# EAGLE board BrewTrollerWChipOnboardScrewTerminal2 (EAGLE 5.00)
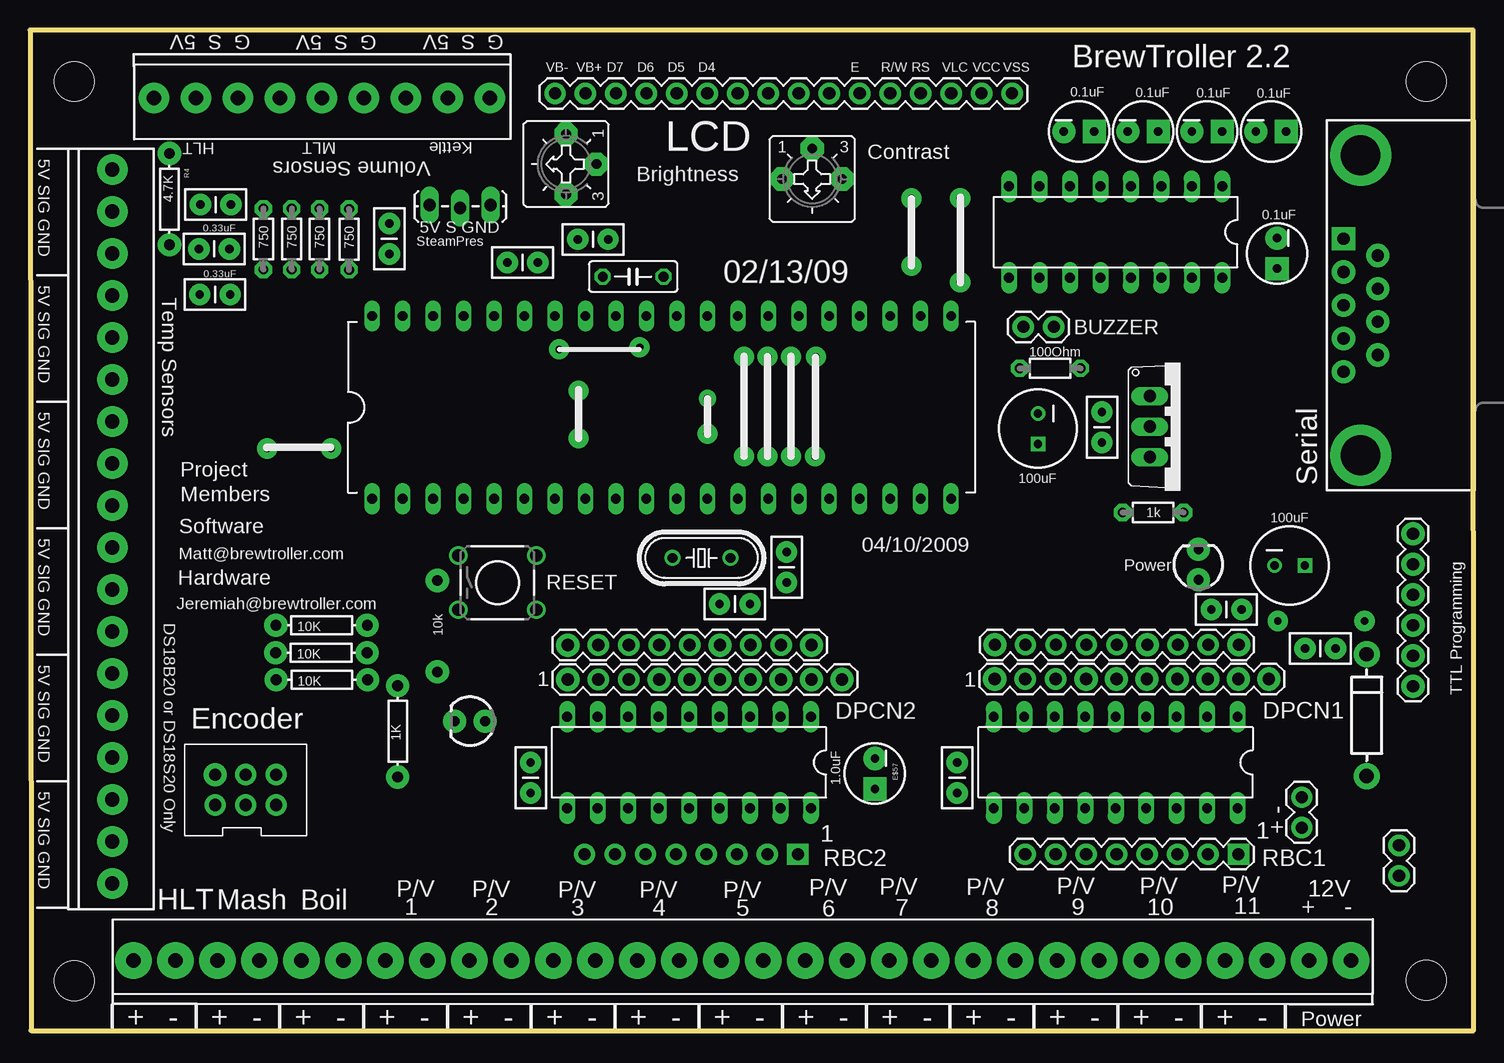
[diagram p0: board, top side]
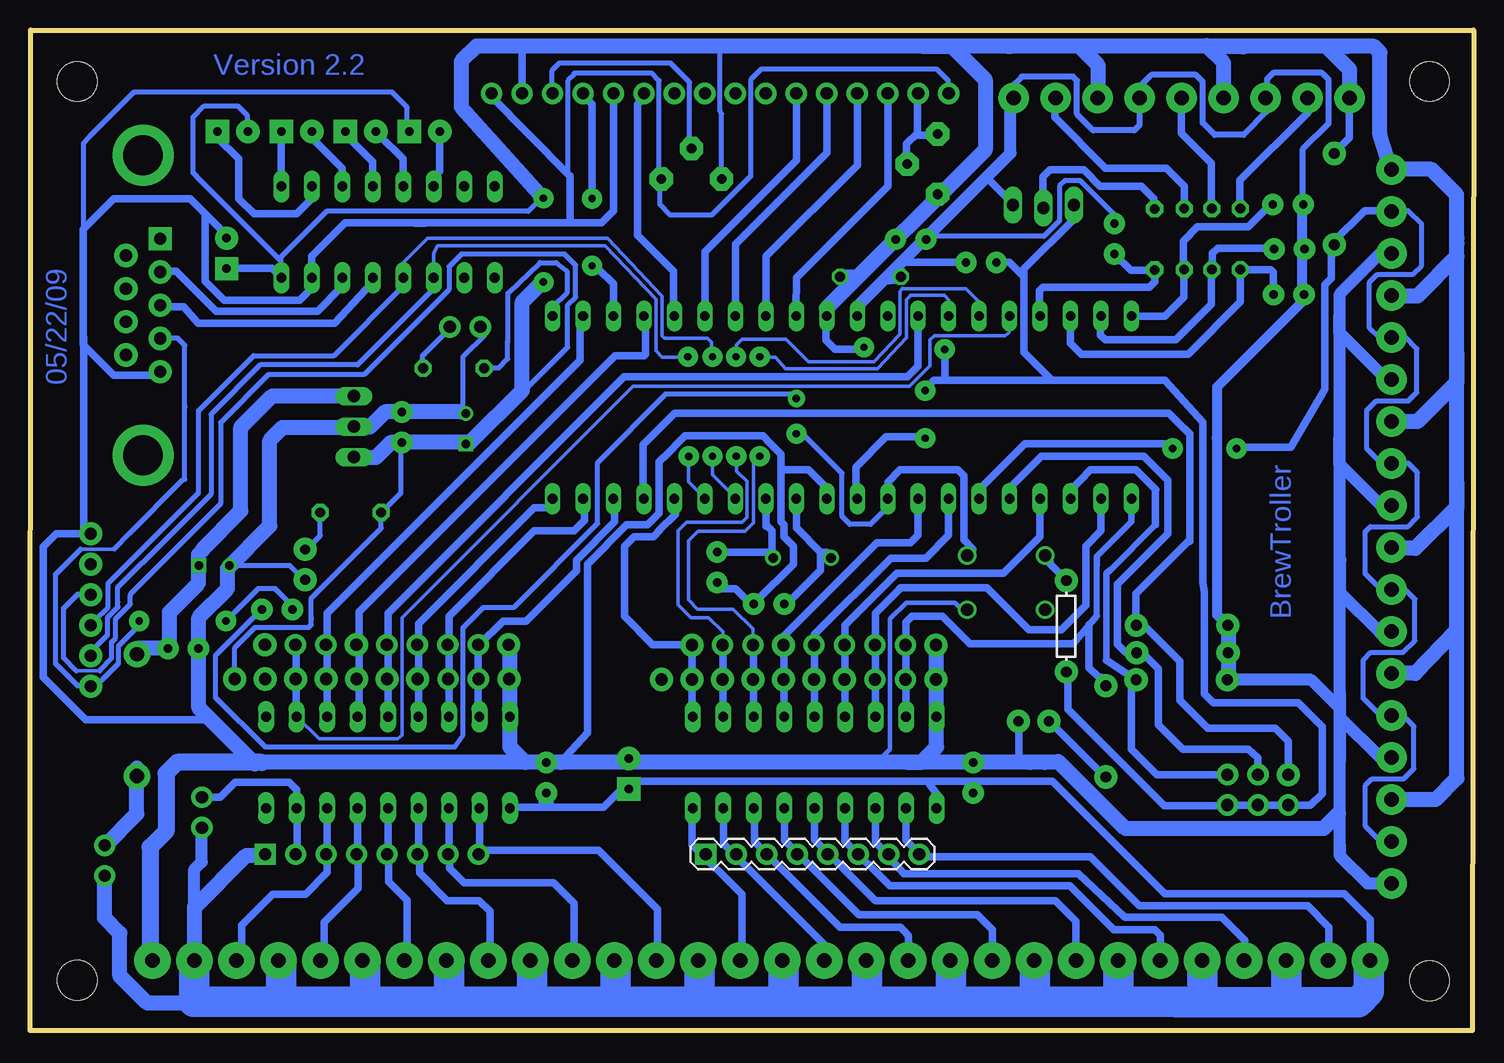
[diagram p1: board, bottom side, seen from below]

Size 120.35 x 83.39 mm. Coordinates in mm from the lower left corner, seen from the top.
Outline: 0.1,0 120.34,0 120.29,83.39 0,83.39 0.1,0
Copper layers (1*16): Top 0.035mm / dielectric 1.5mm / Bottom 0.035mm
Design rules "default *": minimum track width 10mil, minimum drill 24mil, track to track 8mil, track to pad 8mil, pad to pad 8mil, via to via 8mil, smd to smd 8mil, copper to edge 40mil, drill to drill 8mil, minimum pad ring 10mil, minimum via ring 8mil, stop-mask expansion 4mil, vias tented up to drill 0mil, thermal gap 10mil

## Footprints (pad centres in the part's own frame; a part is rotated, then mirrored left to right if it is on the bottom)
1X02 = drill 1.016 pad 1.778 round: 1 0,0; 2 2.54,0
LED3MM = drill 0.813 pad 1.93 round: A -1.27,0; K 1.27,0
HC49/S = drill 0.813 round: 1 -2.413,0; 2 2.413,0
DIL18 = drill 0.813 long: 1 -10.16,-3.81; 2 -7.62,-3.81; 3 -5.08,-3.81; 4 -2.54,-3.81; 5 0,-3.81; 6 2.54,-3.81; 7 5.08,-3.81; 8 7.62,-3.81; 9 10.16,-3.81; 10 10.16,3.81; 11 7.62,3.81; 12 5.08,3.81; 13 2.54,3.81; 14 0,3.81; 15 -2.54,3.81; 16 -5.08,3.81; 17 -7.62,3.81; 18 -10.16,3.81
DB9 = drill 1.016 pad 1.93 square: 1 -5.54,-1.42 | drill 1.016 pad 1.93 round: 2 -2.77,-1.42; 3 0,-1.42; 4 2.77,-1.42; 5 5.54,-1.42; 6 -4.15,1.42; 7 -1.38,1.42; 8 1.38,1.42; 9 4.15,1.42 | drill 3.302 pad 5.08 round: G1 -12.5,0; G2 12.5,0
SCREWTERMINAL3.5MM18P = drill 1.2 pad 2.54 round: 1 -31.496,0; 2 -27.996,0; 3 -24.496,0; 4 -20.996,0; 5 -17.496,0; 6 -13.996,0; 7 -10.496,0; 8 -6.996,0; 9 -3.496,0; 10 0.004,0; 11 3.504,0; 12 7.004,0; 13 10.504,0; 14 14.004,0; 15 17.504,0; 16 21.004,0; 17 24.504,0; 18 28.004,0
CAP-PTH-SMALL2 = drill 0.7 pad 1.778 round: 1 0,0; 2 2.54,0
2X3SHROUDEDHEADER = drill 1.02 pad 1.778 round: P$1 0,2.54; P$3 2.54,5.08; P$4 2.54,2.54; P$5 5.08,5.08; P$6 5.08,2.54 | drill 1.02 pad 1.93 round: P$2 0,5.08
C050-025X075 = drill 0.813 octagon: 1 -2.54,0; 2 2.54,0
DIL40 = drill 0.8 long: 1 -24.13,-7.62; 2 -21.59,-7.62; 3 -19.05,-7.62; 4 -16.51,-7.62; 5 -13.97,-7.62; 6 -11.43,-7.62; 7 -8.89,-7.62; 8 -6.35,-7.62; 9 -3.81,-7.62; 10 -1.27,-7.62; 11 1.27,-7.62; 12 3.81,-7.62; 13 6.35,-7.62; 14 8.89,-7.62; 15 11.43,-7.62; 16 13.97,-7.62; 17 16.51,-7.62; 18 19.05,-7.62; 19 21.59,-7.62; 20 24.13,-7.62; 21 24.13,7.62; 22 21.59,7.62; 23 19.05,7.62; 24 16.51,7.62; 25 13.97,7.62; 26 11.43,7.62; 27 8.89,7.62; 28 6.35,7.62; 29 3.81,7.62; 30 1.27,7.62; 31 -1.27,7.62; 32 -3.81,7.62; 33 -6.35,7.62; 34 -8.89,7.62; 35 -11.43,7.62; 36 -13.97,7.62; 37 -16.51,7.62; 38 -19.05,7.62; 39 -21.59,7.62; 40 -24.13,7.62
CPOL-RADIAL-100UF-25V = drill 0.7 square: 1 1.27,0 | drill 0.7 round: 2 -1.27,0
TO220V = drill 1.016 long: 1 -2.54,-2.54; 2 0,-2.54; 3 2.54,-2.54
0204/5 = drill 0.813 pad 1.422 octagon: 1 -2.54,0; 2 2.54,0
DIL16 = drill 0.813 long: 1 -8.89,-3.81; 2 -6.35,-3.81; 3 -3.81,-3.81; 4 -1.27,-3.81; 5 1.27,-3.81; 6 3.81,-3.81; 7 6.35,-3.81; 8 8.89,-3.81; 9 8.89,3.81; 10 6.35,3.81; 11 3.81,3.81; 12 1.27,3.81; 13 -1.27,3.81; 14 -3.81,3.81; 15 -6.35,3.81; 16 -8.89,3.81
CPOL-RADIAL-10UF-25V = drill 0.7 pad 1.93 square: 1 1.27,0 | drill 0.7 pad 1.93 round: 2 -1.27,0
SCREWTERMINAL3.5MM9P = drill 1.2 pad 2.54 round: 1 0.051,0.102; 2 3.551,0.102; 3 7.051,0.102; 4 10.551,0.102; 5 14.051,0.102; 6 17.551,0.102; 7 21.051,0.102; 8 24.551,0.102; 9 28.051,0.102
1X09 = drill 1.016 pad 1.93 round: 1 0,0; 6 12.7,0; 9 20.32,0 | drill 1.016 pad 1.778 round: 2 2.54,0; 3 5.08,0; 4 7.62,0; 5 10.16,0; 7 15.24,0; 8 17.78,0
1X08 = drill 1.016 pad 1.778 square: 1 0,0 | drill 1.016 pad 1.778 round: 2 2.54,0; 3 5.08,0; 4 7.62,0; 5 10.16,0; 6 12.7,0; 7 15.24,0; 8 17.78,0
1X16 = drill 1.016 pad 1.778 round: 1 0,0; 2 2.54,0; 3 5.08,0; 4 7.62,0; 5 10.16,0; 6 12.7,0; 7 15.24,0; 8 17.78,0; 9 20.32,0; 10 22.86,0; 11 25.4,0; 12 27.94,0; 13 30.48,0; 14 33.02,0; 15 35.56,0; 16 38.1,0
STAND-OFF = hole 3.302: 0,0
1X10 = drill 1.016 pad 1.93 round: 1 0,0; 4 7.62,0; 5 10.16,0; 6 12.7,0; 7 15.24,0; 8 17.78,0; 9 20.32,0; 10 22.86,0 | drill 1.016 pad 1.778 round: 2 2.54,0; 3 5.08,0
AXIAL-0.3 = drill 0.9 pad 1.93 round: P$1 -3.81,0; P$2 3.81,0
SCREWTERMINAL3.5MM30P = drill 1.2 pad 3.048 round: 1 0,0; 2 3.5,0; 3 7,0; 4 10.5,0; 5 14,0; 6 17.5,0; 7 21,0; 8 24.5,0; 9 28,0; 10 31.5,0; 11 35,0; 12 38.5,0; 13 42,0; 14 45.5,0; 15 49,0; 16 52.5,0; 17 56,0; 18 59.5,0; 19 63,0; 20 66.5,0; 21 66.5,0; 22 70,0; 23 73.5,0; 24 77,0; 25 80.5,0; 26 84,0; 27 87.5,0; 28 91,0; 29 94.5,0; 30 98,0; 31 101.5,0
CT6 = drill 0.813 pad 1.93 octagon: A 2.515,0; E -2.515,0; S 0,-2.54
1X03_LOCK_LONGPADS = drill 1.016 long: 1 0,0; 2 2.54,-0.254; 3 5.08,0
DIODE-1N4001 = drill 1.2 pad 2.184 round: A -5.08,0; C 5.08,0
TACTILE-PTH = drill 1.016 round: 1 -3.251,2.261; 2 3.251,2.261; 3 -3.251,-2.261; 4 3.251,-2.261
1X06 = drill 1.016 pad 1.93 round: 1 0,0; 2 2.54,0; 3 5.08,0; 4 7.62,0; 5 10.16,0; 6 12.7,0

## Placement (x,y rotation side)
BUZZER  [1X02]  82.8,58.65 0 top
E$1  Debug  [LED3MM]  36.68,25.78 180 top
E$2  16Mhz  [HC49/S]  55.98,39.4 180 top
E$3  ULN2803  [DIL18]  54.94,22.35 180 top
E$4  [DB9]  110.92,60.45 270 top
E$5  [SCREWTERMINAL3.5MM18P]  6.86,40.26 270 top
E$6  ULN2803  [DIL18]  90.5,22.35 180 top
E$7  0.33uF  [CAP-PTH-SMALL2]  16.69,61.34 180 top
E$8  [2X3SHROUDEDHEADER]  15.44,16.26 0 top
E$9  1uF  [C050-025X075]  50.28,62.83 180 top
E$10  ATMEGA644p  [DIL40]  52.65,51.94 0 top
E$11  100uF  [CPOL-RADIAL-100UF-25V]  105,38.76 0 top
E$12  100uF  [CPOL-RADIAL-100UF-25V]  84.02,50.16 270 top
E$13  0.1uF  [CAP-PTH-SMALL2]  108.84,31.85 180 top
E$14  0.1uF  [CAP-PTH-SMALL2]  89.36,49.02 90 top
E$15  22pF  [CAP-PTH-SMALL2]  63.07,37.34 90 top
E$16  22pF  [CAP-PTH-SMALL2]  57.48,35.56 0 top
E$17  7805  [TO220V]  95.88,50.34 270 top
E$18  [LED3MM]  97.41,38.84 90 top
E$19  1k  [0204/5]  93.62,43.18 0 top
E$20  MAX232  [DIL16]  90.5,66.55 180 top
E$21  0.1uF  [CPOL-RADIAL-10UF-25V]  98.12,74.93 0 top
E$22  0.1uF  [CPOL-RADIAL-10UF-25V]  92.79,74.93 0 top
E$23  0.1uF  [CPOL-RADIAL-10UF-25V]  103.45,74.93 0 top
E$24  [SCREWTERMINAL3.5MM9P]  38.38,77.83 180 top
E$25  750  [0204/5]  19.46,65.96 270 top
E$26  100nF  [CAP-PTH-SMALL2]  41.73,19.81 90 top
E$27  0.1uF  [CAP-PTH-SMALL2]  101.02,35.1 180 top
E$28  750  [0204/5]  21.82,65.96 270 top
E$29  750  [0204/5]  24.13,65.96 270 top
E$30  0.1uF  [CPOL-RADIAL-10UF-25V]  103.96,64.77 270 top
E$31  0.1uF  [CPOL-RADIAL-10UF-25V]  87.45,74.93 0 top
E$32  10k  [1X09]  44.83,32.13 0 top
E$33  750  [0204/5]  26.59,65.94 270 top
E$34  [1X08]  64.01,14.71 0 bottom
E$35  [1X08]  100.74,14.71 180 top
E$36  100Ohm  [0204/5]  85.04,55.19 180 top
E$37  10K  [1X09]  80.44,32.16 0 top
E$38  [1X16]  81.86,78.11 180 top
E$39  SteamHeat  [1X02]  106.02,16.92 90 top
E$40  [STAND-OFF]  3.68,4.17 0 top
E$41  [STAND-OFF]  3.68,79.1 0 top
E$42  [STAND-OFF]  116.41,79.1 0 top
E$43  [STAND-OFF]  116.41,4.19 0 top
E$44  [1X10]  44.83,29.26 0 top
E$45  [1X10]  80.42,29.31 0 top
E$46  0.33uF  [CAP-PTH-SMALL2]  29.95,67.26 270 top
E$47  100nF  [CAP-PTH-SMALL2]  77.29,19.81 90 top
E$48  0.33uF  [CAP-PTH-SMALL2]  16.64,65.15 180 top
E$49  0.33uF  [CAP-PTH-SMALL2]  16.74,68.83 180 top
E$50  10k  [AXIAL-0.3]  33.96,33.71 270 bottom
E$51  0.1uF  [CAP-PTH-SMALL2]  48.19,65.95 180 top
E$52  [SCREWTERMINAL3.5MM30P]  8.64,5.84 0 top
E$53  100Ohm  [CT6]  44.68,72.21 90 top
E$54  10K  [CT6]  65.2,70.97 180 top
E$55  1K  [AXIAL-0.3]  30.66,24.94 90 top
E$56  SteamPres  [1X03_LOCK_LONGPADS]  33.32,68.81 0 top
E$57  1.0uF  [CPOL-RADIAL-10UF-25V]  70.43,21.41 270 top
E$58  0.15uF  [CAP-PTH-SMALL2]  42.33,64.01 180 top
E$59  Switch  [1X02]  114.12,12.9 90 top
E$60  [DIODE-1N4001]  111.43,26.29 90 top
R1  10K  [AXIAL-0.3]  24.31,33.78 0 top
R2  10K  [AXIAL-0.3]  24.28,31.5 0 top
R3  10K  [AXIAL-0.3]  24.33,29.24 0 top
R4  4.7K  [AXIAL-0.3]  11.62,69.29 270 top
RESET  Reset  [TACTILE-PTH]  38.96,37.34 0 top
TTLPROG  DTR TX RX 5V N/C GND  [1X06]  115.29,28.7 90 top

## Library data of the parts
BUZZER E$1 E$3 E$4 E$6 E$7 E$10-E$18 E$20-E$23 E$26 E$27 E$30-E$32 E$34 E$35 E$37-E$51 E$55-E$60 R1-R4 RESET TTLPROG = SparkFun
E$2 = crystal
E$5 E$8 E$24 E$52 = Personal
E$9 = rcl
E$19 E$25 E$28 E$29 E$33 E$36 = rc-master
E$53 E$54 = pot

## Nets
S$22: E$3.5
S$65: E$10.13
S$105: E$6.11
S$255: E$3.9 E$6.9
S$257: E$39.1

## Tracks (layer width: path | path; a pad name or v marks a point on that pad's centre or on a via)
S$1
  Bottom 1.27: 93.29,52.91 100.15,52.91 102.77,50.29 102.77,43.31 105.94,40.13 105.94,40.06 106.3,39.7 106.3,37.29 108.71,34.87 108.71,32.16 108.74,31.88 111.23,31.88
S$2
  Bottom 0.61: 31.22,21.59 31.22,21.62 34.92,25.32
S$3
  Bottom 0.61: 67.82,41.73 68.38,41.17 70,41.17 70.79,40.39 70.79,36.02
S$4
  Bottom 0.61: 66.52,43.87 66.52,43.05 67.89,41.68
S$5
  Bottom 0.305: 63.55,56.29 63.55,57.38 63.86,57.68 67.44,57.68 67.64,57.91
S$6
  Bottom 0.61: 58.47,39.88 62.56,39.88
S$7
  Bottom 0.61: 62.81,36.83 61.54,36.83 60.53,35.81 59.77,35.81 56.72,38.86 56.72,40.39 57.48,41.15 57.48,42.16 57.73,42.42 57.73,46.48 57.48,46.74 55.45,46.74 53.92,45.21
S$8
  Bottom 0.381: 42.82,35.26 43.23,35.66 47.3,35.66 48.64,34.32 48.64,23.47 49.43,22.68 49.73,22.68
S$9  (via drill 0.6 pad 1.68)
  other vias: 63.45,47.88
S$10
  Bottom 0.61: 49.86,26.72 49.86,34.8 47.83,36.83
S$11
  Bottom 0.61: 52.4,33.02 52.4,33.78 48.08,38.1 39.19,38.1 36.14,41.15 36.14,44.04
S$12
  Bottom 0.61: 48.84,45.21 48.84,45.72 47.83,46.74 43,46.74 42.49,46.23 42.49,40.89 41.73,40.13
S$13
  Bottom 0.559: 31.42,34.57 33.38,32.26
  Bottom 0.61: 47.32,26.03 47.32,34.04 46.81,34.54 44.27,34.54 41.99,32.26 33.38,32.26
S$14
  Bottom 2.54: 27.64,2.41 106.71,2.41
S$15
  Bottom 0.61: 94.36,61.98 96.37,59.97 104.83,59.97 108.15,63.3 108.69,63.27
S$16
  Bottom 0.61: 33.6,45.01 31.95,46.74 28.14,46.74 26.49,45.08
S$17
  Bottom 0.61: 80.37,32.13 80.42,32.18
S$18
  Bottom 0.61: 52.4,26.47 52.4,32.89
S$19
  Bottom 0.61: 37.92,25.27 37.92,22.38 38,22.3
S$20
  Bottom 0.61: 38.81,45.08 36.02,47.88 27.51,47.88 25.48,45.85
S$21
  Bottom 0.61: 24.08,50.16 23.65,49.73 23.65,40.92 | 23.65,40.92 23.65,40.79 | 28.17,36.32 28.17,36.4 23.65,40.92
S$22
  Bottom 0.61: 43.76,43.69 43.76,41.27 45.67,39.37 48.59,39.37 54.94,33.02 E$3.5
S$23
  Bottom 0.61: 41.22,45.08 37.41,48.89 25.22,48.89
S$24
  Bottom 0.61: 99.44,62.79 100.18,63.53 103.66,63.53
S$25
  Bottom 0.61: 99.39,70.26 99.39,74.42
S$26
  Bottom 0.635: 80.4,18.61 72.53,18.61 70.37,20.76 45.54,20.76 44.78,19.75
S$27
  Bottom 2.54: 24.14,2.41 27.57,2.41
S$28
  Bottom 2.54: 29.6,3.24 29.6,5.84
S$29
  Bottom 2.54: 36.59,3.17 36.59,5.84
S$30
  Bottom 2.54: 43.57,3.11 43.57,5.84
S$31
  Bottom 2.54: 57.54,3.17 57.54,5.84
S$32
  Bottom 2.54: 64.53,2.79 64.53,5.84
S$33
  Bottom 2.54: 71.51,3.17 71.51,5.84
S$34
  Bottom 2.54: 78.5,3.11 78.5,5.84
S$35
  Bottom 2.54: 85.42,3.05 85.42,5.84
S$36
  Bottom 2.54: 92.41,3.17 92.41,5.84
S$37
  Bottom 2.54: 99.39,3.37 99.39,5.84
S$38  (via drill 0.6 pad 1.68)
  other vias: 25.1,48.51
S$39
  Bottom 2.54: 50.56,2.86 50.56,5.84
S$40
  Bottom 0.406: 107.44,45.95 107.44,52.04
S$41
  Bottom 0.61: 12.09,6.55 12.09,8.64 13.84,10.39 27.86,10.39 31.95,14.48 45.92,14.48 47.32,15.87 47.32,17.6 47.37,17.65
S$42
  Bottom 0.61: 19.07,6.53 19.07,7.52 21.01,9.45 29.08,9.45 32.97,13.06 47.47,13.06 49.86,15.72 49.86,17.6
S$43
  Bottom 0.61: 26.11,6.58 26.11,7.95 26.57,8.41 30,8.41 33.66,12.06 48.67,12.06 52.4,15.8 52.4,17.63 52.43,17.65
S$44
  Bottom 0.61: 54.97,17.7 54.89,17.63
S$45
  Bottom 0.61: 33.15,6.65 33.15,9.12 34.87,10.85 49.89,10.85 54.94,15.9 54.94,17.58 54.91,17.6
S$46
  Bottom 0.61: 40.13,6.58 40.13,8.41 41.38,9.65 51.23,9.65 57.43,15.85
S$47
  Bottom 0.61: 57.45,17.68 57.45,15.9
S$48
  Bottom 0.61: 82.91,17.58 82.88,17.6
S$49
  Bottom 0.61: 90.5,17.58 90.47,17.55
S$50
  Bottom 0.61: 88.9,5.87 88.9,10.87 90.45,12.42 90.45,15.14
S$51
  Bottom 0.61: 95.63,17.58 95.53,17.68
S$52
  Bottom 0.406: 81.84,78.05 81.89,78.1
S$53  (via drill 0.6 pad 1.68)
  other vias: 19.76,48.51
S$54
  Bottom 0.61: 46.3,43.56 46.3,41.27 46.94,40.64 49.73,40.64 57.48,32.89 57.48,25.91
S$55
  Bottom 0.61: 96.85,74.42 94.31,71.88 94.31,70.76
S$56
  Bottom 0.61: 93.8,74.42 91.77,72.39 91.77,70.79
S$57
  Bottom 0.61: 47.12,6.63 47.12,7.92 47.55,8.36 47.55,8.38 47.78,8.61 52.83,8.61 59.97,15.75 59.97,17.91
S$58
  Bottom 0.61: 56.46,44.2 56.46,41.91 54.43,39.88 | 54.43,39.88 53.92,39.88 | 54.43,39.88 54.43,38.35 56.97,35.81
S$59
  Bottom 0.61: 91.26,74.68 89.23,72.64 89.23,70.87
S$60
  Bottom 0.61: 86.69,71.12 86.18,71.63 86.18,74.68
S$61
  Bottom 0.61: 104.72,74.42 102.95,72.64 102.95,69.34 101.68,68.07 98.12,68.07 96.88,69.32 | 96.88,69.32 96.85,69.34 | 96.88,69.32 96.88,70.31
S$62
  Bottom 0.61: 92.3,61.77 94.94,58.95 106.32,58.95 107.52,60.32 108.84,60.32
S$63
  Bottom 1.016: 39.65,72.09 51.51,60.22 51.51,60.15 | 39.65,72.09 39.27,72.47 | 38.61,76.76 38.61,73.13 39.65,72.09
S$64
  Bottom 0.61: 69.24,44.83 69.24,48.82 66.6,51.46 25.43,51.46 23.67,49.71
S$65
  Bottom 0.61: 59,42.16 59,42.04 | 59,42.16 E$10.13 | 58.5,40 58.5,41.66 59,42.16
S$66
  Bottom 1.27: 92.79,47.75 91.52,47.75 90.25,49.02 83.64,49.02 79.32,53.34 79.32,60.71 77.65,62.38
S$67
  Bottom 0.813: 14.28,69.01 14.28,60.76 21.39,53.64 21.39,49.4 21.41,49.38
S$68
  Bottom 0.305: 64.06,44.37 65.43,45.75 65.43,47.88
S$69
  Bottom 0.61: 82.93,32.11 80.9,34.14 78.99,34.14 74.8,38.33 74.8,39.22 71.63,42.39 71.63,44.3
S$70
  Bottom 0.61: 74.12,43.56 74.12,42.54 75.01,41.66 78.31,41.66 85.42,34.54 85.42,26.03
S$71
  Bottom 0.61: 76.66,43.56 78.31,43.56 87.96,33.91 87.96,26.42
S$72
  Bottom 0.61: 53.9,44.4 53.9,45.14
S$73
  Bottom 0.61: 46.3,58.67 46.3,55.37 47.19,54.48 70.81,54.48 90.5,34.8 90.5,26.03
S$74
  Bottom 0.61: 69.04,58.8 69.04,56.39 69.16,56.26 71.58,56.26 92.91,34.92 92.91,26.54
S$75  (via drill 0.6 pad 1.68)
  other vias: 65.43,47.85
S$76
  Bottom 0.406: 76.73,60.32 75.59,61.47 75.59,63.3 76.48,64.01 77.83,64.01 80.49,61.47 80.49,57.4
S$77
  Bottom 0.61: 98.09,18.54 98.12,18.57 98.12,20.09 98.73,20.7 103.25,20.7 104.5,19.46 105.97,19.46
S$78  (via drill 0.6 pad 1.68)
  other vias: 63.45,56.16
S$79
  Bottom 1.016: 7.8,33.15 11.1,36.45 11.1,39.22
S$80
  Bottom 1.016: 7.75,43.79 11.2,47.24 11.2,49.33
S$81  (via drill 0.6 pad 1.68)
  other vias: 65.51,56.16
S$82
  Bottom 0.305: 61.49,44.37 63.45,46.33 63.45,47.96
S$83
  Bottom 0.61: 74.5,58.8 74.5,55.88 95.58,34.8 95.58,25.78
S$84
  Bottom 0.305: 65.79,56.13 67.64,56.13 68.17,56.64 68.17,60.96 72.41,65.4 86.36,65.4 86.69,64.77 86.69,63.5
S$85
  Bottom 0.305: 67.44,57.68 67.64,57.91 67.64,61.21 72.21,66.04 87.2,66.04 89.23,64.01 89.23,63.5
S$86
  Bottom 0.61: 50.95,56.77 53.24,56.77 53.98,57.53 53.98,59.54
S$87
  Bottom 0.406: 66.47,22.53 66.5,22.56
S$88  (via drill 0.6 pad 1.68)
  other vias: 73.48,63.75
S$89  (via drill 0.6 pad 1.68)
  Bottom 0.61: v73.48,69.34 73.48,77.19 73.81,77.52
S$90
  Bottom 0.61: 71.7,60.2 71.7,62.23 72.97,63.5
S$91
  Bottom 1.016: 7.34,54.33 11.2,58.19 11.2,59.51
S$92
  Bottom 0.61: 62.56,26.62 62.56,32.41
S$93
  Bottom 0.406: 4.72,42.75 5.46,42.01 8.61,42.01 9.04,41.58 9.04,38.07 7.8,36.83 5.77,36.83 4.9,35.97 4.9,32.51 5.89,31.52 8.56,31.52 9.22,30.86 9.22,27.69 7.8,26.26 5.89,26.26 4.98,25.35 4.98,21.84 5.84,20.98 8.48,20.98 9.02,20.45 9.02,17.02 7.77,15.77
S$94
  Bottom 0.61: 66.7,60.38 66.7,63.3 69.7,66.29 69.7,77.22 69.49,77.42
S$95
  Bottom 0.61: 96.85,63.5 96.85,64.52 94.06,67.31 72.72,67.31 71.7,68.33 71.7,77.47
S$96
  Bottom 0.61: 31.01,29.44 31.24,29.44 32.05,30.25 32.05,33.81
S$97
  Bottom 0.406: 5.44,68.3 4.34,67.21 4.34,63.75 5.08,63.02 8.03,63.02 8.69,62.36 8.69,58.55 7.92,57.78 5.66,57.78 4.72,56.85 4.72,53.19 5.44,52.48 8.13,52.48 8.89,51.71 8.89,48.49 7.7,47.29 5.46,47.29 4.7,46.53 4.7,42.8 4.72,42.77
S$98
  Bottom 0.61: 61.54,60.45 61.54,65.53 53.92,73.15 53.92,77.47
S$99
  Bottom 0.61: 58.98,59.94 59,64.52 51.38,72.14 51.38,77.47
S$100
  Bottom 1.27: 106.66,5.82 106.38,5.84
  Bottom 2.54: 106.66,2.44 106.66,5.82
S$101
  Bottom 0.61: 56.49,60.02 56.46,62.74 48.84,70.36 48.84,77.47
S$102  (via drill 0.6 pad 1.68)
  other vias: 77.55,62.38
S$103  (via drill 0.6 pad 1.68)
  other vias: 77.55,69.37
S$104
  Bottom 1.016: 7.72,64.82 11.15,61.39 11.15,28.04 | 11.15,15.44 11.15,14.55 8.84,12.24 6.86,12.24 | 11.15,15.44 11.15,28.04 | 7.8,22.78 11.15,26.14 11.15,28.04 | 11.15,15.44 11.15,14.6
S$105
  Bottom 0.61: E$6.11 82.88,15.06 82.91,15.04 72.95,15.04 68.25,10.34 68.22,10.34 68.02,10.13 68.02,5.84
S$106
  Bottom 0.61: 60.05,26.57 60.02,32.51
S$107
  Bottom 2.54: 24.79,2.39 9.63,2.39 8.74,3.28 8.74,5.79
S$108
  Bottom 2.54: 15.67,5.66 15.6,5.74
S$109
  Bottom 2.54: 17.42,2.36 16.64,2.36
S$110
  Bottom 0.406: 22.62,5.78 22.75,5.91
  Bottom 2.54: 22.62,3.87 22.62,5.78
S$111
  Bottom 2.54: 15.6,2.46 15.6,5.84
S$112
  Bottom 1.27: 34.54,22.35 36.98,22.35
S$113
  Bottom 0.61: 54.08,6.65 54.08,7.14 62.53,15.6 62.53,17.73
S$114
  Bottom 0.61: 61.01,6.58 61.01,11.35 65.15,15.49 65.15,17.65 65.1,17.7
S$115
  Bottom 0.61: 75.01,5.87 75.01,10.62 76.71,12.32 84.15,12.32 85.37,13.54 85.37,14.99 85.4,15.01
S$116
  Bottom 0.305: 61.42,47.88 61.44,47.85 61.44,46.63 60.58,45.77 60.58,42.77 60.98,42.37 65.61,42.37 66.32,41.66 66.32,35.51 65.23,34.42 63.78,34.42 62.59,33.22 62.59,32.03
S$117
  Bottom 1.27: 10.54,82.02 8.31,82.02 7.82,81.53 7.82,74.65 6.86,71.65
S$118
  Bottom 1.27: 6.25,29.77 4.85,29.77 1.42,33.38 1.42,36.17
S$119
  Bottom 0.61: 45.41,53.77 44.98,54.2 42.93,54.2 | 42.93,54.2 43.66,54.2 | 35.15,54.2 25.76,54.2 22.58,50.7 22.58,37.36 22.45,36.55 22.45,28.07 21.69,27.3 14.61,27.3 12.62,25.32 12.62,19.76 13.61,18.77 21.03,18.77 | 35.15,54.2 42.93,54.2 | 35.15,54.2 37.49,56.54 37.49,63.47 33.38,67.59 33.38,69.01
S$120
  Bottom 0.61: 7.34,68.33 9.09,68.33 11.86,65.56 11.86,62.71 12.42,62.15 12.42,53.47 15.24,48.62 19.48,48.62 19.63,48.46
S$121
  Bottom 0.61: 21.21,21.34 26.42,21.34 28.52,23.44 28.52,28.5 28.47,28.55
S$122
  Bottom 0.61: 18.01,21.95 18.01,22.76 18.8,23.44 24.26,23.44 26.29,25.48 26.29,30.15 27.58,31.45
S$123
  Bottom 0.61: 15.47,22.1 15.47,24.13 16.54,25.2 22.15,25.2 24.49,27.53 24.49,30.78 27.48,33.78
S$124
  Bottom 0.559: 30.33,38.38 30.61,38.1 30.61,30.86
  Bottom 0.61: 28.78,29.64 30.61,30.86
S$125
  Bottom 0.61: 25.48,45.8 25.48,41.43 29.69,37.21 29.69,32.21 29.03,31.55
S$126
  Bottom 0.61: 28.17,34.44 28.17,36.25
S$127
  Bottom 1.27: 20.4,33.78 20.4,29.21 20.45,29.16
S$128
  Bottom 1.27: 20.27,33.73 20.17,33.83
S$129  (via drill 0.6 pad 1.68)
  other vias: 45.72,53.34
S$130  (via drill 0.6 pad 1.68)
  other vias: 45.72,49.38
S$131
  Bottom 0.61: 51.51,44.65 51.51,46.94 48.97,49.48 46.23,49.48 46.1,49.35
S$132
  Bottom 0.61: 65.15,26.67 65.15,32
S$133
  Bottom 0.61: 16.71,68.86 16.92,68.86 18.8,66.98 23.01,66.98 24.21,65.79 24.21,63.5
S$134
  Bottom 1.27: 19.2,81.99 21.39,81.99
S$135
  Bottom 1.27: 53.98,60.17 40.72,73.41 40.72,79.25 43.51,82.04 46.05,82.04 | 77.52,69.32 84.4,76.96 84.4,80.77 83.13,82.04 46.05,82.04 | 38.96,82.04 46.05,82.04 | 38.96,82.04 38.43,82.04 | 9.73,82.04 38.96,82.04
S$136
  Bottom 1.27: 29.97,82.04 31.09,82.04
S$137
  Bottom 1.27: 1.4,65.61 1.42,69.67 3.53,71.78 6.91,71.78 6.93,71.75
S$138
  Bottom 0.61: 28.04,59.54 25.73,59.54 24.16,61.11 24.16,63.45 24.18,63.47
S$139
  Bottom 0.61: 93.04,17.65 92.99,17.7
S$140
  Bottom 0.61: 92.99,15.06 92.99,11.86 95.81,9.04 95.81,5.87 95.88,5.79
S$141
  Bottom 0.61: 81.99,5.84 81.99,9.93 82.91,10.85 85.57,10.85 87.88,13.16 87.88,15.09
S$142
  Bottom 0.61: 95.56,15.11 95.56,13.18 97.36,11.38 100.13,11.38 102.72,8.79 102.72,5.99 102.82,5.89
S$143
  Bottom 0.61: 85.4,15.06 85.4,18.54 85.47,18.62
S$144
  Bottom 0.61: 87.94,15.06 87.94,18.54
S$145
  Bottom 0.61: 90.5,15.11 90.5,18.49 90.58,18.57
S$146
  Bottom 0.61: 93.01,15.11 93.01,18.44 92.84,18.62 92.89,18.62
S$147
  Bottom 0.61: 95.58,15.01 95.58,18.54 95.56,18.57
S$148
  Bottom 1.016: 20.68,29.26 20.65,29.24 13.54,29.24 11.12,26.82 11.12,22.53
S$149
  Bottom 1.27: 6.17,40.16 6.15,40.18 4.85,40.18 1.4,43.64 1.4,45.59 | 5.99,61.21 4.7,61.21 1.4,64.52 | 6.07,50.75 4.7,50.75 1.4,54.05 1.4,56.44 | 1.4,64.52 1.4,66.04 | 1.4,56.44 1.4,64.52 | 1.4,45.59 1.4,56.44 | 1.4,45.59 1.4,21.03 3.17,19.25 6.96,19.25
S$150
  Bottom 1.27: 31.29,77.72 31.29,80.44 32.92,82.07
S$151
  Bottom 1.27: 20.83,77.7 20.83,80.64 22.28,82.09
S$152
  Bottom 0.61: 16.64,65.2 21.34,65.2 21.77,64.77 21.77,63.65 21.87,63.55
S$153
  Bottom 0.61: 16.69,61.39 16.69,63.2 16.89,63.4 19.25,63.4 19.33,63.47
S$154
  Bottom 0.813: 20.52,33.78 21.39,34.65 21.39,49.86
S$155
  Bottom 1.27: 10.34,77.72 10.34,80.09 12.27,82.02
S$156
  Bottom 0.61: 13.84,77.67 13.84,76.5 19.48,70.87 19.48,68.58
S$157
  Bottom 0.61: 96.88,61.87 97.87,60.88 104.16,60.88 105.74,62.46 105.74,68.07 | 109.55,54.86 109.8,54.61 113.36,54.61 115.9,57.15 115.9,66.8 113.36,69.34 107.01,69.34 105.74,68.07 | 105.74,68.07 103.96,66.29
S$158
  Bottom 0.61: 21.87,60.53 24.84,57.56 30.71,57.56 31.11,57.96 31.11,58.62
S$159
  Bottom 0.61: 19.48,60.68 23.77,56.39 32.72,56.39 33.63,57.3 33.63,58.78
S$160
  Bottom 0.61: 38.56,73.02 38.56,74.65
S$161
  Bottom 0.305: 38.76,59.31 38.76,58.17 39.09,57.91 44.96,57.91 45.31,57.56 45.31,55.42 47.04,53.7 70.08,53.7 89.33,34.42 89.33,24.64 89.69,24.31 96.24,24.31 98.15,26.21
S$162
  Bottom 0.61: 98.17,26.09 98.17,32.05 98.3,32.18 98.27,32.18 98.2,32.26
S$163
  Bottom 0.305: 47.6,61.85 47.83,61.57 47.83,58.01 49.99,55.73 55.45,55.73
S$164
  Bottom 0.305: 46.96,61.24 47.3,60.91 47.3,57.73 49.71,55.14 57.38,55.14 58.19,56.13 59.41,56.13 59.41,56.16
S$165
  Bottom 0.406: 29.97,67.26 29.97,68.02 32.79,70.84 34.09,70.84 34.52,70.41 34.52,67.51 35.84,66.19 45.39,66.19 45.41,66.22
S$166
  Bottom 0.406: 80.52,57.51 80.52,55.98 81.28,55.22 82.3,55.22
S$167
  Bottom 0.406: 82.42,57.99 84.23,56.18 84.23,51.38
S$168
  Bottom 0.61: 115.88,47.9 115.88,57.84
S$169  (via drill 0.6 pad 1.68)
  Bottom 0.406: 115.19,28.37 112.98,30.58 112.98,32.05 111.25,33.78 v111.25,34.14 111.25,34.19
S$170
  Bottom 0.61: 115.88,47.75 115.88,41.96 115.39,41.48
S$171
  Bottom 1.27: 94.56,50.29 92.02,50.29 90.75,51.56 84.4,51.56
S$172
  Bottom 0.406: 113.82,37.29 106.3,44.81
S$173
  Bottom 0.61: 24.36,77.75 24.36,74.78 21.87,72.29 21.87,68.94
S$174
  Bottom 1.27: 93.19,50.27 99.29,50.27 100.35,49.2 100.35,42.06 103.89,38.53 103.89,36.83 106.27,34.44 106.27,26.9 101.6,22.22
S$175
  Bottom 0.61: 34.92,77.8 34.92,76.1 30.71,71.88 25.63,71.88 24.13,70.38 24.13,68.99 24.16,68.96
S$176
  Bottom 0.61: 32.33,40.39 31.06,41.66 31.06,44.2
S$177
  Bottom 0.61: 65.15,32.16 68.45,32.16 70.79,34.54 70.79,36.3
S$178
  Bottom 0.508: 31.42,34.62 31.42,38.79 31.42,39.17
  Bottom 0.533: 31.42,38.79 31.42,39.52 28.52,42.42 28.52,44.12
S$179
  Bottom 0.61: 47.88,36.83 47.8,36.91 40.56,36.91 37.08,33.43 34.37,33.43 32.33,35.46 32.33,40.31
S$180
  Bottom 0.61: 34.52,38.1 35.28,38.86 35.28,38.99
S$181
  Bottom 0.61: 20.6,18.75 25.78,18.75 33.83,26.8 33.83,29.06 33.91,29.13
S$182
  Bottom 0.61: 79.32,78.05 79.32,81.84 79.15,82.02
S$183
  Bottom 1.27: 111.43,21.89 111.43,18.06 114.12,15.37 114.05,15.37
S$184
  Bottom 0.61: 11.63,73.15 10.36,74.42 10.36,77.77
S$185
  Bottom 0.61: 46.38,77.39 46.38,74.78 47.27,73.89 47.27,72.52
S$186
  Bottom 0.61: 45.21,74.63 46.38,74.63 46.43,74.68
S$187
  Bottom 0.406: 43.79,78.74 43.79,79.17 44.73,80.11 59.41,80.11 60.27,79.22 60.27,71.2 63.52,67.97 66.95,67.97 67.84,68.86 67.84,70.82 67.72,70.94
S$188
  Bottom 0.406: 76.86,78.74 76.86,79.98 76.22,80.62 66.95,80.62 65.35,79.02 65.35,74.02
S$189
  Bottom 0.406: 68.5,79.78 68.48,79.78 | 68.5,79.78 74.88,79.78 | 74.88,79.78 75.01,79.78 | 68.5,79.78 67.89,79.17 67.89,71.3 | 74.88,79.78 75.51,79.15 75.51,71.42
  Bottom 0.61: 75.34,67.34 75.34,71.25 75.51,71.42 81.89,77.85
S$190
  Bottom 0.61: 89.89,48.67 89.84,48.72
S$191
  Bottom 0.406: 96.9,34.42 96.9,34.26 | 96.9,34.42 96.9,36.04 91.06,41.88 91.06,43.15 89.41,44.81 89.41,49.12 | 96.9,34.42 96.9,33.81 97.1,33.6 101.57,33.6 103.28,31.9 103.28,29.51 103.45,29.34 103.43,29.34
S$192
  Bottom 0.406: 109.91,43.61 107.57,45.95
S$193
  Bottom 0.406: 5.46,68.33 6.5,68.33 6.5,68.3
S$194
  Bottom 0.406: 84.35,51.87 84.56,51.66
S$195
  Bottom 0.406: 113.84,35.26 113.84,37.26
S$196
  Bottom 0.533: 39.98,22.5 39.93,22.56
S$197
  Bottom 0.559: 30.3,38.38 26.54,42.14
  Bottom 0.61: 26.54,42.14 26.54,45.08
S$198  (via drill 0.6 pad 1.68)
  other vias: 50.83,56.95
S$199
  Bottom 1.27: 106.5,2.29 110.57,2.29 112.85,4.57 112.85,8.13 114.12,9.4 114.12,12.19
S$200
  Bottom 0.406: 99.47,62.97 99.47,64.44 95.63,68.28 78.82,68.28 77.62,69.47
S$201
  Bottom 0.406: 88.9,74.88 88.9,76.94 90.17,78.21 111.68,78.21 115.39,74.5 115.39,74.47 115.9,73.96 115.9,65.86 115.8,65.76
S$202
  Bottom 0.406: 99.42,62.76 99.42,64.11 106.43,71.12 106.43,71.15 106.76,71.48 106.76,76.12 105.82,77.06 103.02,77.06 102.24,76.28 102.24,74.88 102.21,74.85 102.18,74.85
S$203
  Bottom 0.406: 62.69,70.99 62.69,76.4 62.81,76.61 62.81,81.94 62.87,81.97
S$204
  Bottom 0.61: 56.46,75.06 56.46,74.93 | 56.46,75.06 56.46,77.47 | 64.08,60.45 64.08,64.9 56.46,72.52 56.46,75.06
S$205
  Bottom 0.406: 89.23,62.03 95,56.26 101.7,56.26 106.3,51.66 106.3,44.83
S$206
  Bottom 1.27: 100.91,14.6 102.31,14.6 106.63,10.29 106.63,6.73
S$207
  Bottom 0.762: 44.81,19.71 44.83,19.68 44.83,18.64
S$208
  Bottom 0.61: 48.84,44.53 48.84,45.14
S$209
  Bottom 0.406: 67.89,71.42 67.92,71.45
S$210
  Bottom 0.508: 14.22,68.78 14.22,73.48 12.09,75.62 12.09,79.25 12.65,79.81 16.71,79.81 17.22,79.3 17.22,76.61 19.18,74.65 21.59,74.65 22.58,75.64 22.58,79.1 23.14,79.65 26.85,79.65 27.86,78.64 27.86,75.46 28.3,75.03 31.73,75.03 33.07,76.38 33.07,79.17 33.4,79.5 37.67,79.5 38.56,78.61
S$211
  Bottom 0.61: 105.36,25.91 115.7,25.91 119.25,29.46 119.25,40.31 118.16,41.4 115.24,41.4 115.21,41.38
S$212
  Bottom 0.61: 88.24,67.28 87.45,67.28
S$213
  Bottom 0.406: 112.04,41.45 109.91,43.59
S$214  (via drill 0.6 pad 1.68)
  Bottom 0.406: 56.62,49.71 56.59,49.73 v56.46,49.73
S$215  (via drill 0.6 pad 1.42)
  other vias: 56.46,52.68
S$216
  Bottom 0.406: 101.12,35.03 104.88,31.27 104.88,27.76 100.71,23.62
S$217
  Bottom 0.406: 55.91,49.71 52.65,46.46 52.65,42.85 51.99,42.19 50.27,42.19 48.9,43.56
S$218
  Bottom 0.406: 103.89,34.26 101.32,36.83 99.9,36.83 98.53,35.46 98.53,35.18
S$219
  Bottom 1.27: 47.7,62.86 47.75,62.81 48.74,62.81
S$220
  Bottom 1.27: 52.83,62.84 52.78,62.79 51.41,62.79
S$221
  Bottom 0.406: 97.49,37.57 98.68,38.76 103.81,38.76
S$222
  Bottom 0.406: 56.44,53.04 67.39,53.04
S$223
  Bottom 0.406: 110.11,43.38 109.93,43.56
S$224
  Bottom 0.406: 110.95,39.01 113.03,36.96 113.03,35.38
S$225
  Bottom 0.406: 86.66,61.85 93.04,55.47 101.14,55.47 105.26,51.36 105.26,44.7 111,38.96
S$226
  Bottom 0.406: 111.96,36.4 104.47,43.89 104.47,50.67 100.48,54.66 92.51,54.66 91.21,55.96 | 91.21,55.96 91.24,55.93 | 91.21,55.96 85.42,61.75 85.42,63.68 84.38,64.72 75.77,64.72 74.85,63.8 74.85,61.14 75.51,60.48 75.51,56.95 79.48,52.98
S$227
  Bottom 0.305: 116.13,40.13 113.31,40.13
  Bottom 0.406: 113.31,40.13 112.04,41.45 | 116.13,40.13 118.21,38.05 118.21,30.56 116.38,28.73 115.29,28.73
S$228
  Bottom 0.61: 9.7,5 9.68,5.03
S$229
  Bottom 0.406: 113.84,35.43 113.84,35.26 114.94,34.16 114.91,34.16 114.88,34.19
S$230
  Bottom 0.406: 115.34,31.14 115.34,31.52 113.87,32.99 113.87,34.44 113.03,35.28 113.03,35.74
S$231
  Bottom 0.305: 114.53,29.97 116.48,29.97
  Bottom 0.406: 111.99,36.27 111.99,35.53 113.21,34.32 113.21,32.72 113.54,32.38 113.54,31.04 114.53,29.97 | 115.52,36.37 116.38,36.37 117.55,35.2 117.55,31.06 116.48,29.97
S$232
  Bottom 0.61: 8.64,5.69 8.64,9.25 10.79,11.4 12.32,11.4 | 46,20.78 35.13,20.78 25.76,11.4 12.32,11.4 | 12.32,11.4 11.71,11.4
S$233
  Bottom 0.406: 107.42,51.92 107.44,51.94 107.44,57.1 108.05,57.71 109.58,57.71
S$234  (via drill 0.6 pad 1.68)
  other vias: 104.01,34.14
S$235
  Bottom 0.406: 97.41,39.98 96.14,41.25 96.14,43.28
S$236
  Bottom 0.406: 85.34,58.52 87.63,56.24 87.63,55.09
S$237
  Bottom 0.305: 59.54,47.78 60.05,47.27 60.05,42.32 60.73,41.63 64.67,41.63 65.46,40.84 65.46,35.89 64.69,35.13 61.72,35.13 60.07,33.48 60.07,32.23
S$238
  Bottom 0.61: 82.75,26.16 82.88,26.03 82.75,26.03
S$239
  Bottom 0.406: 67.31,53.06 73.03,47.35 73.03,42.27 80.01,35.28 82.55,35.28 84.25,33.58 84.25,24.64 84.94,23.62 100.71,23.62
S$240  (via drill 0.6 pad 1.68)
  Bottom 0.61: 44.09,54.25 v44.09,56.77
S$241
  Bottom 0.305: 46.96,61.26 44.12,61.26 43.74,60.88 43.74,59.72
S$242  (via drill 0.6 pad 1.68)
  other vias: 61.47,47.88
S$243  (via drill 0.6 pad 1.68)
  other vias: 59.51,47.88
S$244  (via drill 0.6 pad 1.68)
  other vias: 61.49,56.16
S$245  (via drill 0.6 pad 1.68)
  other vias: 59.51,56.16
S$246
  Bottom 0.305: 55.45,55.73 57.33,57.63 60.98,57.63 61.44,57.18 61.44,56.16
S$247
  Bottom 0.61: 98.09,18.52 98.09,14.71 98.12,14.68
S$248
  Bottom 0.61: 19.43,60.76 19.43,63.37 19.41,63.4
S$249
  Bottom 0.61: 21.87,60.6 21.87,63.45 21.92,63.5
S$250
  Bottom 0.61: 36.2,59.54 36.2,61.65 35.89,61.95 27.03,61.95 26.57,62.41 26.57,63.45
S$251
  Bottom 0.61: 26.54,63.35 28.57,63.35 29.9,64.67
S$252
  Bottom 0.61: 26.64,68.63 26.64,69.34 27.69,70.38 31.14,70.38 32.49,71.73 35.31,71.73 35.89,71.15
S$253
  Bottom 0.61: 35.92,71.09 35.92,68.94 35.99,68.86
S$254
  Bottom 0.406: 40.28,70.79 40.28,71.53
  Bottom 0.61: 40.28,70.79 38.51,69.01
S$255
  Bottom 0.406: 77.8,22.35 79.07,22.35
  Bottom 0.61: 57.76,46.15 57.76,48.03 58.67,48.95 58.67,48.97 59.26,49.56 65.73,49.56 67.54,47.75 67.56,47.75 67.92,47.4 67.92,43.1 68.88,42.14 70.61,42.14 73.86,38.89 73.86,24.84 76.1,22.35
  Bottom 1.27: 80.47,32.13 80.34,32.13 E$6.9 80.34,23.62 79.07,22.35 | 44.78,25.78 E$3.9 | 44.78,25.78 44.78,32.13 | 44.78,25.78 44.78,23.62 46.05,22.35 47.19,22.35 | 101.68,22.35 101.02,22.35 77.8,22.35 76.1,22.35 47.19,22.35 | 35.76,22.35 47.19,22.35
  Bottom 1.422: 110.16,5.66 110.34,5.84 110.34,15.29 108.99,16.64 108.99,21.44 108.08,22.35 101.02,22.35
S$256
  Bottom 0.61: 108.66,16.92 109.47,16.1
S$257
  Bottom 1.016: 106.68,9.68 106.66,9.7 106.66,13.44 106.02,14.07 E$39.1
S$258
  Bottom 1.27: 34.62,22.43 29.03,16.84 12.52,16.84 11.25,18.11
S$259
  Bottom 0.406: 77.32,19.84 77.27,19.86
  Bottom 1.27: 77.32,19 77.32,19.84
S$260
  Bottom 1.422: 41.71,19.68 41.76,19.68 41.76,20.29
S$261
  Bottom 0.305: 42.29,61.77 41.25,60.73 41.25,59.64
S$262
  Bottom 0.61: 37.57,62.92 38.68,64.03 39.73,64.03
S$263
  Bottom 0.61: 42.47,63.98 42.52,64.03 47.52,64.03
S$264
  Bottom 0.305: 42.34,61.82 47.65,61.82 47.65,61.77
S$265
  Bottom 0.61: 82.98,32.21 82.98,26.11

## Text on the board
Bottom: Version 2.2 | 05/22/09 | BrewTroller
tPlace: VB- | VB+ | D7 | D6 | D5 | D4 | E | R/W | RS | VLC | VCC | VSS | LCD | Contrast | Brightness | P/V | P/V | P/V | P/V | P/V | P/V | P/V | P/V | P/V | P/V | P/V | HLT | Mash | Boil | 11 | 1 | 2 | 3 | 4 | 5 | 6 | 7 | 8 | 9 | 10
tNames: G S 5V | G S 5V | G S 5V | BrewTroller 2.2 | HLT | MLT | Kettle | 5V SIG GND | Volume Sensors | 5V S GND | SteamPres | 5V SIG GND | 02/13/09 | Temp Sensors | Serial | 5V SIG GND | Project | Members | 5V SIG GND | Software | 04/10/2009 | Matt@brewtroller.com | Power | Hardware | Jeremiah@brewtroller.com | DS18B20 or DS18S20 Only | 5V SIG GND | 1 | 1 | TTL Programming | DPCN2 | DPCN1 | Encoder | 5V SIG GND | 1 | 1 | + - | RBC2 | RBC1 | 12V | + | - | + | - | + | - | + | - | + | - | + | - | + | - | + | - | + | - | + | - | + | - | + | - | + | - | + | - | + | - | Power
